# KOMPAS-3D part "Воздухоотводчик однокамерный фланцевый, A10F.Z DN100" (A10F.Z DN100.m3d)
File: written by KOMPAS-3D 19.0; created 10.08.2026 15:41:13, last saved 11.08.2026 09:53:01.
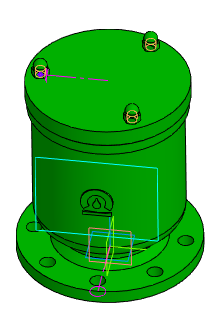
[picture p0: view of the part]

Document properties: Автор: Энергия; Полное имя файла: Z:\3.Личные\kachalov\001_3d для проектировщиков\x.x Тип A10F.Z Воздухоотводчик однокамерный фланцевый\A10F.Z DN100.m3d

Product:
- Part/product: Воздухоотводчик однокамерный фланцевый  | designation A10F.Z DN100
    Масса: 34.7835
  - Component [standard]: Гайка М12-6H (S18) ГОСТ 11860-85  | qty 3  | Масса: 0.02606; Раздел спецификации: Стандартные изделия; Рассекать на разрезах: no; source file: C:\Program Files\ASCON\KOMPAS-3D v19\Libs\PARTLib\DATA\vault\Methods\Kompas\3D\PLib_Blind_Nut_type1_900.m3d

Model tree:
1. Эскиз:1
2. Элемент вращения:1
     Угол 1 = 360
3. Скругление:1  (with: Элемент вращения:1)
     Радиус = 10
4. Фаска:1  (with: Элемент вращения:1)
     Угол = 45; Длина 1 = 10; Длина 2 = 10
5. Эскиз:2  (with: Элемент вращения:1)
6. Точка:1
     Y = -80; Z = 248; Координата Y = -80; Координата Z = 248
7. Массив по концентрической сетке:1  (with: Элемент вращения:1)  (3 pattern instances)
     Шаг 2 = 360
8. Эскиз:3  (with: Элемент вращения:1)
9. Элемент выдавливания:1  (with: Элемент вращения:1, Массив по концентрической сетке:1, Эскиз:3)  (8 pattern instances)
     Расстояние 2 = 16; N 1 = 1; Шаг 1 = 10; Шаг 2 = 360; Номер 1 = 1
10. Касательная плоскость:1  (with: Элемент вращения:1)
11. Эскиз:4
12. Элемент выдавливания:2  (with: Элемент вращения:1)  (labels: Фаска наружная:1)
     Расстояние 1 = 1; Ориентация = 2

Expressions: Dn/2; D2/2; D/2; B/2; D1/2; H/2; D1-20
Referenced files in C:\Program Files\ASCON\KOMPAS-3D v19\Libs\PARTLib\DATA\vault\Methods\Kompas\3D\: PLib_Blind_Nut_type1_900.m3d
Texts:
  A10F.Z DN100
  Гайка М12-6H (S18) ГОСТ 11860-85 (1)
  foc1
  foc2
